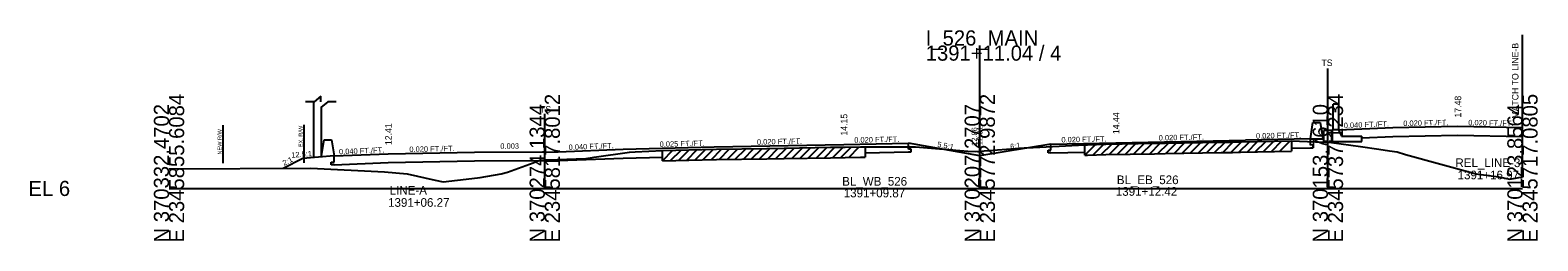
# Model space of a CAD drawing. Extents: x -170 to 2527928, y -10 to 1619750.
# Drawn here: x 1974.3 to 2253.3, y 4490.3 to 4529.3 of the extents above; entities that cross this region are included whole.
import ezdxf

# ---------------------------------------------------------------- set-up
doc = ezdxf.new("R2010")
doc.units = 0
for name, color, linetype in [('Default', 7, 'Continuous'), ('RD_GPK_XS_Cell', 7, 'Continuous'), ('RD_PD_NOISE-WALL-GM', 7, 'Continuous'), ('RD_PD_WallFill', 7, 'Continuous'), ('RD_XS_Base', 7, 'Continuous'), ('RD_XS_EarthShd', 7, 'Continuous'), ('RD_XS_ExGround', 7, 'Continuous'), ('RD_XS_ExPaveRet', 7, 'Continuous'), ('RD_XS_ExRW', 7, 'Continuous'), ('RD_XS_MatchLine', 7, 'Continuous'), ('RD_XS_NewRW', 7, 'Continuous'), ('RD_XS_Pave', 7, 'Continuous'), ('RD_XS_PaveShd', 7, 'Continuous'), ('RD_XS_TieSlope', 7, 'Continuous'), ('RD_XS_TX_Elev_EX', 7, 'Continuous'), ('RD_XS_TX_Elev_PR', 7, 'Continuous'), ('RD_XS_TX_Slope', 7, 'Continuous'), ('RD_XS_TX_Station', 7, 'Continuous')]:
    doc.layers.add(name, color=color, linetype=linetype)

msp = doc.modelspace()

# ---------------------------------------------------------------- linework, layer by layer
at = {"layer": 'Default'}
for p, q in [((2028.11, 4517.04), (2026.86, 4516.01)), ((2028.11, 4516.01), (2028.11, 4517.04)), ((2026.86, 4516.01), (2025.28, 4516.01)), ((2029.36, 4516.01), (2028.11, 4514.99)), ((2030.95, 4516.01), (2029.36, 4516.01))]:
    msp.add_line(p, q, dxfattribs=at)
at = {"layer": 'RD_GPK_XS_Cell'}
for p, q in [((2150.01, 4500), (2150.01, 4526.42)), ((2000, 4500), (2069.52, 4500)), ((2069.52, 4500), (2150.01, 4500)), ((2150.01, 4500), (2214.42, 4500)), ((2214.42, 4500), (2250.42, 4500))]:
    msp.add_line(p, q, dxfattribs=at)
at = {"layer": 'RD_PD_NOISE-WALL-GM'}
for p, q in [((2026.73, 4516.01), (2026.73, 4505.69)), ((2028.23, 4505.81), (2028.23, 4515.09)), ((2211.18, 4509.16), (2211.66, 4512.16)), ((2211.66, 4512.16), (2213, 4512.16)), ((2213, 4512.16), (2213.48, 4509.16)), ((2028.23, 4506), (2028.71, 4509)), ((2028.71, 4509), (2030.05, 4509)), ((2030.05, 4509), (2030.53, 4506))]:
    msp.add_line(p, q, dxfattribs=at)
at = {"layer": 'RD_PD_WallFill'}
for p, q in [((2215.42, 4510.84), (2215.42, 4515.6)), ((2216.42, 4515.6), (2215.42, 4515.6)), ((2216.42, 4510.84), (2216.42, 4515.6)), ((2215.3, 4510.84), (2215.13, 4510.68)), ((2215.21, 4510.76), (2215.21, 4508.68)), ((2216.42, 4510.84), (2215.3, 4510.84)), ((2216.42, 4510.84), (2216.42, 4510.68)), ((2250.42, 4502.13), (2250.42, 4511.24)), ((2213.64, 4508.68), (2213.64, 4510.68)), ((2215.14, 4510.68), (2213.64, 4510.68)), ((2214.14, 4508.68), (2213.64, 4508.68)), ((2214.14, 4508.54), (2214.14, 4508.68)), ((2214.64, 4508.52), (2214.64, 4508.68)), ((2215.14, 4508.68), (2214.64, 4508.68)), ((2215.14, 4508.68), (2215.14, 4510.68)), ((2215.21, 4510.68), (2215.14, 4510.68)), ((2215.14, 4508.68), (2220.71, 4508.68)), ((2215.21, 4508.68), (2215.14, 4508.68)), ((2216.42, 4510.68), (2216.92, 4509.68)), ((2216.92, 4509.68), (2220.71, 4509.68)), ((2220.71, 4508.68), (2220.71, 4509.68))]:
    msp.add_line(p, q, dxfattribs=at)
at = {"layer": 'RD_XS_Base'}
for p, q in [((2136.84, 4507.25), (2136.84, 4508.39)), ((2163.18, 4507.06), (2163.18, 4508.2)), ((2211.18, 4508.02), (2211.18, 4509.16)), ((2211.68, 4508.03), (2211.18, 4508.02)), ((2211.68, 4507.53), (2211.68, 4508.03)), ((2220.71, 4509.38), (2226.42, 4509.61)), ((2226.42, 4509.61), (2238.42, 4509.85)), ((2238.42, 4509.85), (2250.42, 4509.61)), ((2030.53, 4504.86), (2030.53, 4506)), ((2072.07, 4505.14), (2084.01, 4505.61)), ((2084.01, 4505.61), (2091.28, 4505.8)), ((2128.82, 4506.59), (2136.84, 4506.75)), ((2137.34, 4507.26), (2136.84, 4507.25)), ((2136.84, 4506.75), (2137.34, 4506.76)), ((2137.34, 4506.76), (2137.34, 4507.26)), ((2162.68, 4507.05), (2163.18, 4507.06)), ((2162.68, 4506.55), (2162.68, 4507.05)), ((2163.18, 4506.56), (2162.68, 4506.55)), ((2163.18, 4506.56), (2169.46, 4506.69)), ((2207.66, 4507.45), (2211.18, 4507.52)), ((2211.18, 4507.52), (2211.68, 4507.53)), ((2030.03, 4504.84), (2030.53, 4504.86)), ((2030.03, 4504.34), (2030.03, 4504.84)), ((2030.53, 4504.36), (2030.03, 4504.34)), ((2030.53, 4504.36), (2040.53, 4504.76)), ((2040.53, 4504.76), (2056.53, 4505.08)), ((2056.53, 4505.08), (2072.07, 4505.14))]:
    msp.add_line(p, q, dxfattribs=at)
at = {"layer": 'RD_XS_EarthShd'}
msp.add_line((2030.53, 4506), (2024.77, 4505.54), dxfattribs=at)
at = {"layer": 'RD_XS_ExGround'}
msp.add_lwpolyline([(2000, 4503.63), (2026.21, 4503.73), (2039.84, 4503.08), (2044.06, 4502.72), (2049.22, 4501.52), (2050.7, 4501.23), (2056.04, 4501.82), (2057.59, 4502.02), (2061.45, 4502.7), (2062.63, 4503.03), (2067.39, 4504.72), (2068.63, 4505.23), (2069.52, 4505.26), (2070.03, 4505.28), (2077.12, 4505.5), (2078.66, 4505.76), (2085.17, 4506.7), (2086.24, 4506.78), (2091.28, 4507.02), (2098.64, 4507.19), (2101.28, 4507.25), (2110.63, 4507.41), (2113.8, 4507.47), (2122.4, 4507.6), (2125.12, 4507.63), (2127.95, 4507.67), (2128.82, 4507.68), (2130.06, 4507.68), (2138.14, 4507.71), (2147.8, 4506.91), (2149.26, 4506.8), (2150.01, 4506.86), (2158.24, 4507.5), (2158.49, 4507.52), (2158.58, 4507.52), (2158.7, 4507.53), (2169.46, 4508.06), (2169.95, 4508.08), (2173.32, 4508.18), (2182.32, 4508.34), (2184.32, 4508.37), (2194.67, 4508.55), (2196.78, 4508.58), (2198.22, 4508.6), (2207.66, 4508.81), (2212.14, 4508.64), (2214.42, 4508.53), (2215.07, 4508.5), (2220.46, 4507.73), (2223.84, 4507.26), (2225.82, 4506.94), (2227.23, 4506.74), (2228.77, 4506.3), (2241.87, 4502.72), (2245.97, 4502.14), (2248.06, 4501.73), (2250.42, 4502.13)], dxfattribs=at)
at = {"layer": 'RD_XS_ExPaveRet'}
for p, q in [((2169.46, 4506.14), (2171.44, 4508.12)), ((2169.46, 4506.14), (2169.46, 4508.06)), ((2170.96, 4506.19), (2172.94, 4508.17)), ((2172.46, 4506.24), (2174.43, 4508.2)), ((2173.96, 4506.28), (2175.91, 4508.23)), ((2175.46, 4506.3), (2177.41, 4508.25)), ((2176.96, 4506.33), (2178.91, 4508.28)), ((2178.46, 4506.35), (2180.41, 4508.3)), ((2179.96, 4506.38), (2181.91, 4508.33)), ((2181.46, 4506.4), (2183.41, 4508.36)), ((2182.96, 4506.43), (2184.91, 4508.38)), ((2184.46, 4506.46), (2186.41, 4508.41)), ((2185.96, 4506.48), (2187.91, 4508.43)), ((2187.46, 4506.51), (2189.41, 4508.46)), ((2188.96, 4506.53), (2190.91, 4508.48)), ((2190.46, 4506.56), (2192.41, 4508.51)), ((2191.96, 4506.58), (2193.91, 4508.53)), ((2193.46, 4506.61), (2195.41, 4508.56)), ((2194.96, 4506.64), (2196.91, 4508.59)), ((2196.46, 4506.66), (2198.41, 4508.61)), ((2197.96, 4506.68), (2199.92, 4508.64)), ((2199.46, 4506.71), (2201.42, 4508.67)), ((2200.96, 4506.75), (2202.92, 4508.7)), ((2202.46, 4506.78), (2204.42, 4508.74)), ((2203.96, 4506.81), (2205.92, 4508.77)), ((2205.46, 4506.84), (2207.42, 4508.8)), ((2207.66, 4508.81), (2207.66, 4506.89)), ((2091.28, 4505.11), (2093.24, 4507.07)), ((2091.28, 4505.11), (2091.28, 4507.02)), ((2091.28, 4505.11), (2098.64, 4505.27)), ((2092.78, 4505.14), (2094.74, 4507.1)), ((2094.28, 4505.17), (2096.24, 4507.13)), ((2095.78, 4505.21), (2097.74, 4507.17)), ((2097.28, 4505.24), (2099.24, 4507.2)), ((2098.64, 4505.27), (2101.28, 4505.33)), ((2098.78, 4505.27), (2100.74, 4507.23)), ((2100.28, 4505.31), (2102.23, 4507.26)), ((2101.28, 4505.33), (2110.63, 4505.49)), ((2101.78, 4505.34), (2103.73, 4507.29)), ((2103.28, 4505.36), (2105.23, 4507.31)), ((2104.78, 4505.39), (2106.73, 4507.34)), ((2106.28, 4505.42), (2108.23, 4507.37)), ((2107.78, 4505.44), (2109.73, 4507.39)), ((2109.28, 4505.47), (2111.23, 4507.42)), ((2110.63, 4505.49), (2113.8, 4505.55)), ((2110.78, 4505.49), (2112.73, 4507.45)), ((2112.28, 4505.52), (2114.23, 4507.47)), ((2113.78, 4505.55), (2115.72, 4507.5)), ((2113.8, 4505.55), (2122.4, 4505.68)), ((2115.28, 4505.57), (2117.22, 4507.52)), ((2116.78, 4505.6), (2118.72, 4507.54)), ((2118.28, 4505.62), (2120.22, 4507.56)), ((2119.78, 4505.64), (2121.72, 4507.59)), ((2121.28, 4505.66), (2123.22, 4507.61)), ((2122.4, 4505.68), (2125.12, 4505.71)), ((2122.78, 4505.68), (2124.72, 4507.62)), ((2124.28, 4505.7), (2126.22, 4507.64)), ((2125.12, 4505.71), (2127.95, 4505.75)), ((2125.78, 4505.72), (2127.72, 4507.66)), ((2127.95, 4505.75), (2128.82, 4505.76)), ((2128.82, 4507.68), (2128.82, 4505.76)), ((2169.46, 4506.14), (2169.95, 4506.16)), ((2169.95, 4506.16), (2173.32, 4506.27)), ((2173.32, 4506.27), (2182.32, 4506.42)), ((2182.32, 4506.42), (2184.32, 4506.45)), ((2184.32, 4506.45), (2194.67, 4506.63)), ((2194.67, 4506.63), (2196.78, 4506.67)), ((2196.78, 4506.67), (2198.22, 4506.69)), ((2198.22, 4506.69), (2207.66, 4506.89))]:
    msp.add_line(p, q, dxfattribs=at)
at = {"layer": 'RD_XS_ExRW'}
msp.add_line((2025, 4504.73), (2025, 4511.73), dxfattribs=at)
at = {"layer": 'RD_XS_MatchLine'}
for p, q in [((2250.42, 4502.13), (2250.42, 4528.37)), ((2214.42, 4500), (2214.42, 4522.15)), ((2069.52, 4500), (2069.52, 4513.78))]:
    msp.add_line(p, q, dxfattribs=at)
at = {"layer": 'RD_XS_NewRW'}
msp.add_line((2010, 4504.67), (2010, 4511.67), dxfattribs=at)
at = {"layer": 'RD_XS_Pave'}
for p, q in [((2226.42, 4511.24), (2238.42, 4511.48)), ((2238.42, 4511.48), (2250.42, 4511.24)), ((2100.84, 4507.67), (2124.84, 4508.15)), ((2175.18, 4508.44), (2199.18, 4508.92)), ((2040.53, 4506.4), (2056.53, 4506.72)), ((2084.01, 4507.25), (2100.84, 4507.67))]:
    msp.add_line(p, q, dxfattribs=at)
at = {"layer": 'RD_XS_PaveShd'}
for p, q in [((2216.42, 4510.84), (2226.42, 4511.24)), ((2124.84, 4508.15), (2136.84, 4508.39)), ((2163.18, 4508.2), (2175.18, 4508.44)), ((2211.18, 4509.16), (2199.18, 4508.92)), ((2211.18, 4509.16), (2213.64, 4509.16)), ((2030.53, 4506), (2040.53, 4506.4)), ((2056.53, 4506.72), (2072.01, 4506.77)), ((2072.01, 4506.77), (2084.01, 4507.25))]:
    msp.add_line(p, q, dxfattribs=at)
at = {"layer": 'RD_XS_TieSlope'}
for p, q in [((2150.01, 4506.01), (2136.84, 4508.39)), ((2163.18, 4508.2), (2150.01, 4506.01)), ((2024.77, 4505.54), (2021.12, 4503.71))]:
    msp.add_line(p, q, dxfattribs=at)

# ---------------------------------------------------------------- texts
at = {"layer": 'RD_GPK_XS_Cell'}
for s, p in [('I_526_MAIN', (2140.01, 4526.42)), ('1391+11.04 / 4', (2140.01, 4523.62)), ('EL 6', (1974, 4498.6))]:
    msp.add_text(s, height=2.8, dxfattribs=at).set_placement(p)
for s, p in [('E 2345855.6084', (2002.8, 4490)), ('E 2345817.8012', (2072.32, 4490)), ('E 2345772.9872', (2152.81, 4490)), ('E 2345737.1234', (2217.22, 4490)), ('E 2345717.0805', (2253.22, 4490)), ('N 370332.4702', (2000, 4490)), ('N 370274.1344', (2069.52, 4490)), ('N 370207.2707', (2150.01, 4490)), ('N 370153.7610', (2214.42, 4490)), ('N 370123.8564', (2250.42, 4490))]:
    msp.add_text(s, height=2.8, rotation=90, dxfattribs=at).set_placement(p)
at = {"layer": 'RD_XS_ExRW'}
msp.add_text('EX. R/W ', height=0.75, rotation=90, dxfattribs=at).set_placement((2024.75, 4507.61))
at = {"layer": 'RD_XS_MatchLine'}
msp.add_text('MATCH TO LINE-B', height=1.2, rotation=90, dxfattribs=at).set_placement((2249.68, 4512.91))
for p in [(2213.23, 4522.63), (2068.66, 4514.03)]:
    msp.add_text('TS', height=1.2, dxfattribs=at).set_placement(p)
at = {"layer": 'RD_XS_NewRW'}
msp.add_text('NEW R/W ', height=0.75, rotation=90, dxfattribs=at).set_placement((2009.75, 4506.25))
at = {"layer": 'RD_XS_TX_Elev_EX'}
msp.add_text('12.86', height=1, rotation=90, dxfattribs=at).set_placement((2149.51, 4507.86))
at = {"layer": 'RD_XS_TX_Elev_PR'}
msp.add_text('12.01', height=1, rotation=90, dxfattribs=at).set_placement((2150.51, 4508.01))
at = {"layer": 'RD_XS_TX_Slope'}
for s, rotation, p in [('0.040 FT./FT.', 2.2906, (2217.37, 4511.13)), ('0.020 FT./FT.', 1.1458, (2228.37, 4511.53)), ('0.020 FT./FT.', 358.8542, (2240.38, 4511.69)), ('0.003', 0.1918, (2061.3, 4507.33)), ('0.040 FT./FT.', 2.2906, (2073.95, 4507.1)), ('0.025 FT./FT.', 1.4321, (2090.78, 4507.67)), ('0.020 FT./FT.', 1.1458, (2108.79, 4508.08)), ('0.020 FT./FT.', 1.1458, (2126.79, 4508.44)), ('5.5:1', 349.732, (2142.09, 4507.69)), ('6:1', 9.4623, (2155.72, 4507.21)), ('0.020 FT./FT.', 1.1458, (2165.12, 4508.49)), ('0.020 FT./FT.', 1.1458, (2183.12, 4508.85)), ('0.020 FT./FT.', 1.1458, (2201.12, 4509.21)), ('2:1', 26.5651, (2021.3, 4504.16)), ('12.5:1', 4.5739, (2022.66, 4505.66)), ('0.040 FT./FT.', 2.2906, (2031.47, 4506.29)), ('0.020 FT./FT.', 1.1458, (2044.48, 4506.73))]:
    msp.add_text(s, height=1, rotation=rotation, dxfattribs=at).set_placement(p)
at = {"layer": 'RD_XS_TX_Station'}
for s, p in [(' 17.48', (2239.08, 4512.66)), (' 14.15', (2125.5, 4509.32)), (' 14.44', (2175.83, 4509.61)), (' 12.41', (2041.19, 4507.57))]:
    msp.add_text(s, height=1.2, rotation=90, dxfattribs=at).set_placement(p)
for s, p in [('REL_LINE-3', (2238.02, 4503.94)), ('BL_EB_526', (2175.37, 4500.79)), ('1391+16.97', (2238.42, 4501.68)), ('LINE-A', (2040.83, 4498.85)), ('BL_WB_526', (2124.55, 4500.51)), ('1391+09.87', (2124.84, 4498.35)), ('1391+12.42', (2175.18, 4498.64)), ('1391+06.27', (2040.53, 4496.6))]:
    msp.add_text(s, height=1.6, dxfattribs=at).set_placement(p)

doc.saveas('drawing.dxf')
